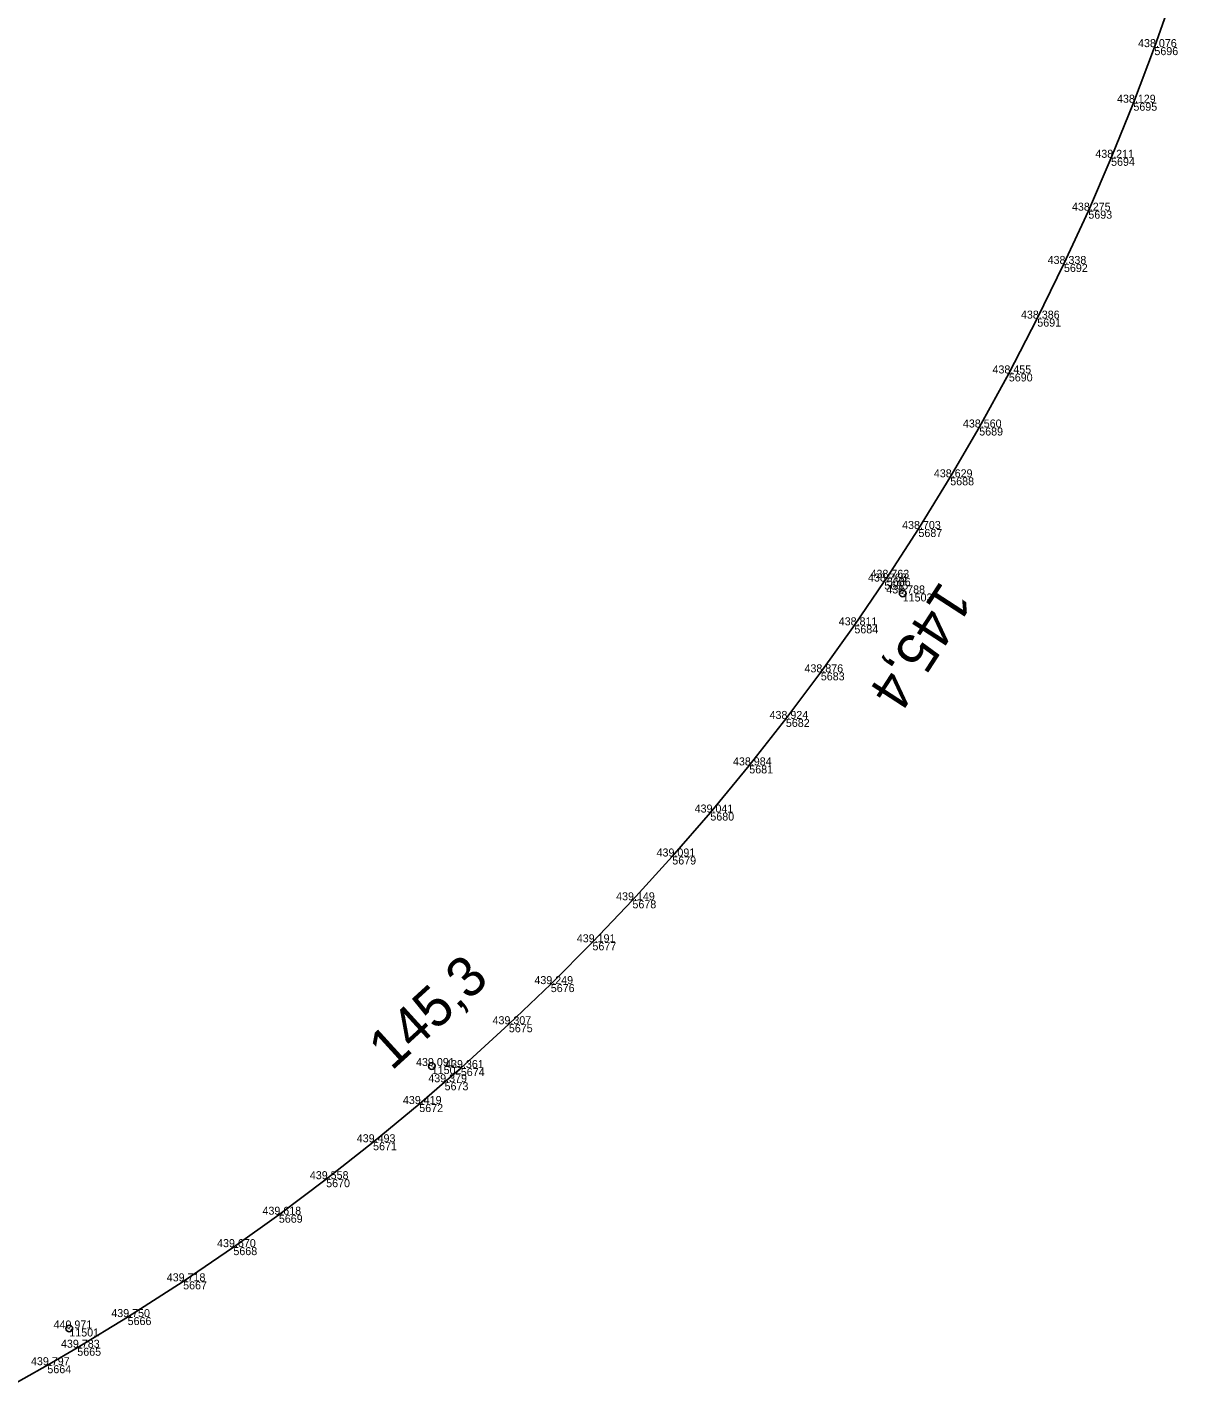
# Model space of a CAD drawing. Extents: x -654154 to -652650, y -1166925 to -1164904.
# Drawn here: x -652851.3 to -652678.7, y -1166869.1 to -1166664.4 of the extents above; entities that cross this region are included whole.
import ezdxf

# ---------------------------------------------------------------- set-up
doc = ezdxf.new("R2010")
doc.units = 0
for name, color, linetype in [('Vrstva 1', 7, 'Continuous'), ('Vrstva 50', 7, 'Continuous'), ('Vrstva 60', 7, 'Continuous'), ('Vrstva 61', 7, 'Continuous'), ('Vrstva 7', 7, 'Continuous')]:
    doc.layers.add(name, color=color, linetype=linetype)

msp = doc.modelspace()

# ---------------------------------------------------------------- linework, layer by layer
at = {"layer": 'Vrstva 1'}
msp.add_lwpolyline([(-652855.35, -1166869.08), (-652848.24, -1166865.11), (-652843.75, -1166862.49), (-652836.2, -1166857.89), (-652827.87, -1166852.53), (-652820.33, -1166847.4), (-652813.51, -1166842.54), (-652806.41, -1166837.21), (-652799.37, -1166831.67), (-652792.44, -1166825.94), (-652788.64, -1166822.67), (-652786.21, -1166820.54), (-652779, -1166813.97), (-652772.71, -1166807.95), (-652766.46, -1166801.68), (-652760.46, -1166795.38), (-652754.48, -1166788.81), (-652748.77, -1166782.22), (-652742.93, -1166775.15), (-652737.44, -1166768.18), (-652732.2, -1166761.19), (-652727.16, -1166754.14), (-652722.67, -1166747.57), (-652722.29, -1166747.01), (-652717.55, -1166739.69), (-652712.78, -1166731.94), (-652708.43, -1166724.47), (-652703.99, -1166716.36), (-652699.72, -1166708.14), (-652695.72, -1166699.94), (-652692.06, -1166691.95), (-652688.65, -1166684.02), (-652685.3, -1166675.76), (-652682.15, -1166667.42), (-652680.05, -1166661.47)], dxfattribs=at)
at = {"layer": 'Vrstva 50'}
msp.add_line((-652845, -1166859.6), (-652844.9, -1166859.6), dxfattribs=at)
msp.add_circle((-652844.95, -1166859.6), 0.5, dxfattribs=at)
at = {"layer": 'Vrstva 60'}
for p, q in [((-652682.15, -1166667.42), (-652682.15, -1166667.42)), ((-652685.3, -1166675.76), (-652685.3, -1166675.76)), ((-652688.65, -1166684.02), (-652688.65, -1166684.02)), ((-652692.06, -1166691.95), (-652692.06, -1166691.95)), ((-652695.72, -1166699.94), (-652695.72, -1166699.94)), ((-652699.72, -1166708.14), (-652699.72, -1166708.14)), ((-652703.99, -1166716.36), (-652703.99, -1166716.36)), ((-652708.43, -1166724.47), (-652708.43, -1166724.47)), ((-652712.78, -1166731.94), (-652712.78, -1166731.94)), ((-652717.55, -1166739.69), (-652717.55, -1166739.69)), ((-652722.67, -1166747.57), (-652722.67, -1166747.57)), ((-652722.29, -1166747.01), (-652722.29, -1166747.01)), ((-652719.91, -1166749.36), (-652719.91, -1166749.36)), ((-652727.16, -1166754.14), (-652727.16, -1166754.14)), ((-652732.2, -1166761.19), (-652732.2, -1166761.19)), ((-652737.44, -1166768.18), (-652737.44, -1166768.18)), ((-652742.93, -1166775.15), (-652742.93, -1166775.15)), ((-652748.77, -1166782.22), (-652748.77, -1166782.22)), ((-652754.48, -1166788.81), (-652754.48, -1166788.81)), ((-652760.46, -1166795.38), (-652760.46, -1166795.38)), ((-652766.46, -1166801.68), (-652766.46, -1166801.68)), ((-652772.71, -1166807.95), (-652772.71, -1166807.95)), ((-652779, -1166813.97), (-652779, -1166813.97)), ((-652790.57, -1166820.24), (-652790.57, -1166820.24)), ((-652786.21, -1166820.54), (-652786.21, -1166820.54)), ((-652788.64, -1166822.67), (-652788.64, -1166822.67)), ((-652792.44, -1166825.94), (-652792.44, -1166825.94)), ((-652799.37, -1166831.67), (-652799.37, -1166831.67)), ((-652806.41, -1166837.21), (-652806.41, -1166837.21)), ((-652813.51, -1166842.54), (-652813.51, -1166842.54)), ((-652820.33, -1166847.4), (-652820.33, -1166847.4)), ((-652827.87, -1166852.53), (-652827.87, -1166852.53)), ((-652836.2, -1166857.89), (-652836.2, -1166857.89)), ((-652844.95, -1166859.6), (-652844.95, -1166859.6)), ((-652843.75, -1166862.49), (-652843.75, -1166862.49)), ((-652848.24, -1166865.11), (-652848.24, -1166865.11))]:
    msp.add_line(p, q, dxfattribs=at)
at = {"layer": 'Vrstva 7'}
for p, q in [((-652719.89, -1166749.32), (-652719.94, -1166749.41)), ((-652790.61, -1166820.27), (-652790.53, -1166820.2))]:
    msp.add_line(p, q, dxfattribs=at)
for centre in [(-652719.91, -1166749.36), (-652790.57, -1166820.24)]:
    msp.add_circle(centre, 0.5, dxfattribs=at)

# ---------------------------------------------------------------- texts
at = {"layer": 'Vrstva 60'}
for s, p in [('5696', (-652682.15, -1166668.62)), ('5695', (-652685.3, -1166676.96)), ('5694', (-652688.65, -1166685.22)), ('5693', (-652692.06, -1166693.15)), ('5692', (-652695.72, -1166701.14)), ('5691', (-652699.72, -1166709.34)), ('5690', (-652703.99, -1166717.56)), ('5689', (-652708.43, -1166725.67)), ('5688', (-652712.78, -1166733.14)), ('5687', (-652717.55, -1166740.89)), ('5685', (-652722.67, -1166748.77)), ('5686', (-652722.29, -1166748.21)), ('11503', (-652719.91, -1166750.56)), ('5684', (-652727.16, -1166755.34)), ('5683', (-652732.2, -1166762.39)), ('5682', (-652737.44, -1166769.38)), ('5681', (-652742.93, -1166776.35)), ('5680', (-652748.77, -1166783.42)), ('5679', (-652754.48, -1166790.01)), ('5678', (-652760.46, -1166796.58)), ('5677', (-652766.46, -1166802.88)), ('5676', (-652772.71, -1166809.15)), ('5675', (-652779, -1166815.17)), ('11502', (-652790.57, -1166821.44)), ('5674', (-652786.21, -1166821.74)), ('5673', (-652788.64, -1166823.87)), ('5672', (-652792.44, -1166827.14)), ('5671', (-652799.37, -1166832.87)), ('5670', (-652806.41, -1166838.41)), ('5669', (-652813.51, -1166843.74)), ('5668', (-652820.33, -1166848.6)), ('5667', (-652827.87, -1166853.73)), ('5666', (-652836.2, -1166859.09)), ('11501', (-652844.95, -1166860.8)), ('5665', (-652843.75, -1166863.69)), ('5664', (-652848.24, -1166866.31))]:
    msp.add_text(s, height=1.2, dxfattribs=at).set_placement(p)
at = {"layer": 'Vrstva 61'}
for s, p in [('438.076', (-652684.6, -1166667.42)), ('438.129', (-652687.76, -1166675.76)), ('438.211', (-652691.01, -1166684.02)), ('438.275', (-652694.52, -1166691.95)), ('438.338', (-652698.17, -1166699.94)), ('438.386', (-652702.17, -1166708.14)), ('438.455', (-652706.44, -1166716.36)), ('438.560', (-652710.88, -1166724.47)), ('438.629', (-652715.24, -1166731.94)), ('438.703', (-652720, -1166739.69)), ('438.768', (-652725.12, -1166747.57)), ('438.763', (-652724.74, -1166747.01)), ('438.788', (-652722.37, -1166749.36)), ('438.811', (-652729.51, -1166754.14)), ('438.876', (-652734.65, -1166761.19)), ('438.924', (-652739.89, -1166768.18)), ('438.984', (-652745.38, -1166775.15)), ('439.041', (-652751.13, -1166782.22)), ('439.091', (-652756.84, -1166788.81)), ('439.149', (-652762.91, -1166795.38)), ('439.191', (-652768.81, -1166801.68)), ('439.249', (-652775.17, -1166807.95)), ('439.307', (-652781.45, -1166813.97)), ('439.091', (-652792.93, -1166820.24)), ('439.361', (-652788.57, -1166820.54)), ('439.379', (-652791.09, -1166822.67)), ('439.419', (-652794.9, -1166825.94)), ('439.493', (-652801.82, -1166831.67)), ('439.558', (-652808.86, -1166837.21)), ('439.618', (-652815.97, -1166842.54)), ('439.670', (-652822.78, -1166847.4)), ('439.718', (-652830.33, -1166852.53)), ('439.750', (-652838.65, -1166857.89)), ('440.971', (-652847.31, -1166859.6)), ('439.783', (-652846.2, -1166862.49)), ('439.797', (-652850.7, -1166865.11))]:
    msp.add_text(s, height=1.2, dxfattribs=at).set_placement(p)
at = {"layer": 'Vrstva 7'}
for s, rotation, p in [('145,4', 237.0494, (-652714.19, -1166747.27)), ('145,3', 42.3432, (-652796.6, -1166821.05))]:
    msp.add_text(s, height=6, rotation=rotation, dxfattribs=at).set_placement(p)

doc.saveas('drawing.dxf')
